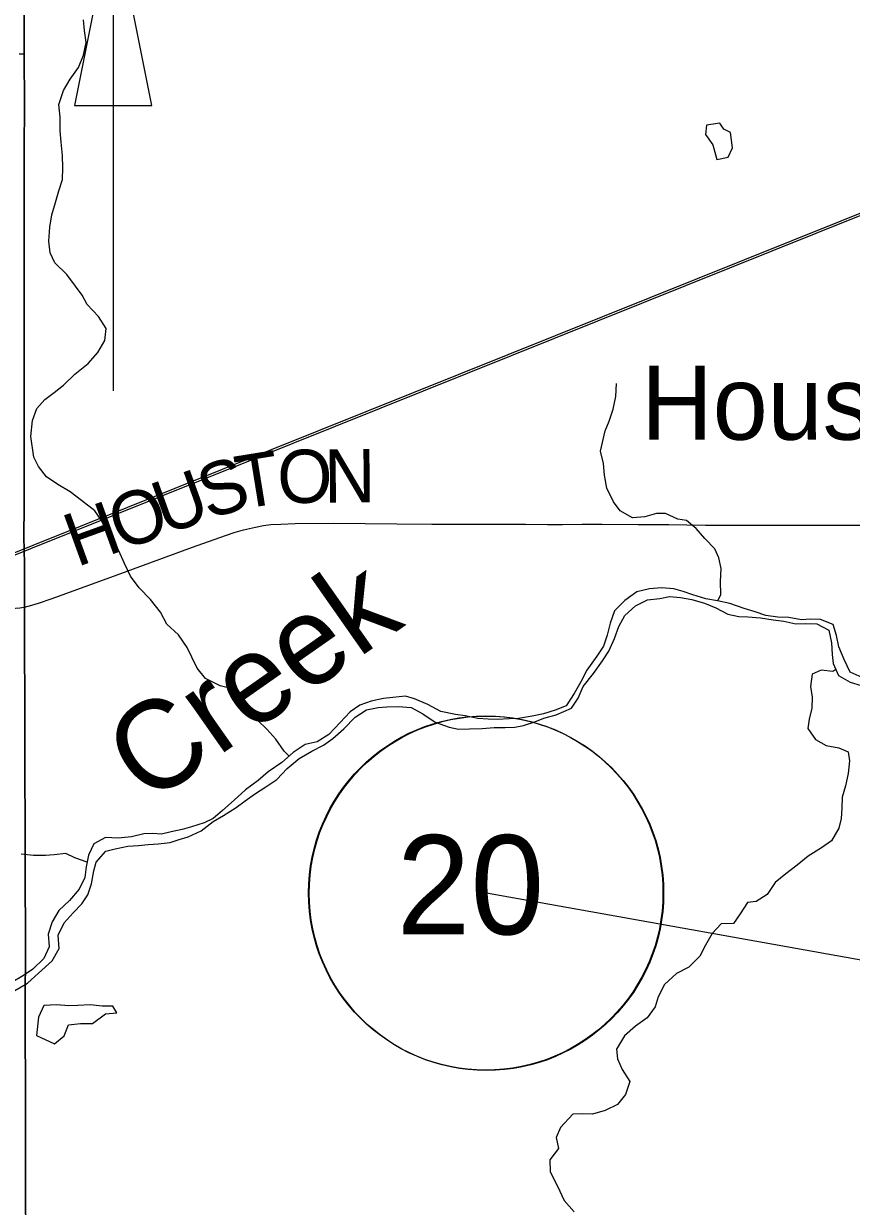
# Model space of a CAD drawing. Extents: x -87 to 2145, y -2128 to 440.
# Drawn here: x 81.45 to 104.8, y 285.55 to 318.92 of the extents above; entities that cross this region are included whole.
import ezdxf

# ---------------------------------------------------------------- set-up
doc = ezdxf.new("R2010")
doc.units = 0
for name, color, linetype in [('BR_P_Gen_Text', 7, 'Continuous'), ('Default', 7, 'Continuous'), ('GM_X_County_Road', 7, 'Continuous'), ('GM_X_County_Road_Text', 7, 'Continuous'), ('GM_X_Minor_Lake', 7, 'Continuous'), ('GM_X_Minor_River', 7, 'Continuous'), ('GM_X_Minor_River_Text', 7, 'Continuous'), ('GM_X_Rail_Line', 7, 'Continuous'), ('GM_X_State_Route', 7, 'Continuous'), ('GM_X_Township_Road', 7, 'Continuous'), ('GM_X_Unincorporated_Text', 7, 'Continuous'), ('SH_Masking', 7, 'Continuous'), ('SH_Text', 7, 'Continuous')]:
    doc.layers.add(name, color=color, linetype=linetype)

msp = doc.modelspace()

# ---------------------------------------------------------------- linework, layer by layer
at = {"layer": 'BR_P_Gen_Text'}
msp.add_lwpolyline([(82.88, 316.612), (85.062, 316.612), (83.971, 322.068)], close=True, dxfattribs=at)
at = {"layer": 'Default'}
msp.add_line((83.971, 322.068), (83.971, 308.561), dxfattribs=at)
for points in [[(81.467, 319.469), (81.46, 318.468), (81.462, 318.07), (81.468, 316.598), (81.464, 315.401), (81.464, 313.597), (81.465, 312.432), (81.463, 311.268), (81.467, 310.021), (81.463, 309.267), (81.465, 308.184), (81.467, 307.167), (81.46, 306.331), (81.465, 305.313), (81.457, 304.444), (81.468, 303.691), (81.474, 302.46), (81.476, 302.116), (81.474, 301.066), (81.478, 300.066), (81.481, 298.343), (81.483, 297.491), (81.489, 296.605), (81.491, 294.981), (81.499, 292.996), (81.499, 292.372), (81.493, 291.714)], [(81.493, 291.714), (81.492, 291.503), (81.496, 290.339), (81.501, 289.076), (81.502, 287.648), (81.497, 286.763), (81.501, 285.943), (81.509, 284.696), (81.516, 283.548), (81.516, 282.334), (81.518, 280.924), (81.526, 279.825), (81.522, 278.972), (81.521, 278.431), (81.529, 277.184), (81.528, 276.298), (81.527, 275.79), (81.535, 274.822), (81.533, 273.69), (81.535, 272.944)]]:
    msp.add_lwpolyline(points, dxfattribs=at)
at = {"layer": 'GM_X_County_Road'}
for points in [[(81.474, 302.46), (81.676, 302.511), (81.866, 302.568), (82.254, 302.701), (84.09, 303.365), (86.215, 304.145), (87.141, 304.477), (87.389, 304.56), (87.656, 304.638), (87.99, 304.717), (88.214, 304.757), (88.424, 304.785), (88.701, 304.803), (89.11, 304.816), (90.192, 304.822), (91.98, 304.81), (92.964, 304.802), (93.669, 304.798), (94.03, 304.797), (94.505, 304.796), (95.03, 304.796), (95.604, 304.795), (96.227, 304.792), (96.654, 304.792), (97.211, 304.794), (97.768, 304.794), (98.785, 304.793), (99.654, 304.789), (100.162, 304.779), (100.687, 304.772), (101.606, 304.769), (102.229, 304.769), (103.13, 304.768), (103.573, 304.769), (103.933, 304.772), (104.211, 304.771), (104.736, 304.769), (105.293, 304.771)], [(77.458, 302.074), (77.604, 302.126), (77.9, 302.219), (78.137, 302.282), (78.328, 302.323), (78.521, 302.356), (78.764, 302.386), (79.024, 302.406), (79.466, 302.42), (79.941, 302.427), (80.433, 302.423), (81.023, 302.42), (81.222, 302.424), (81.338, 302.434), (81.452, 302.455), (81.474, 302.46)]]:
    msp.add_lwpolyline(points, dxfattribs=at)
at = {"layer": 'GM_X_Minor_Lake'}
msp.add_line((84.075, 291.009), (83.966, 291.195), dxfattribs=at)
for points in [[(100.713, 316.053), (100.688, 315.793), (100.892, 315.498), (101.004, 315.085), (101.326, 315.149)], [(101.326, 315.149), (101.451, 315.417), (101.389, 315.85), (101.201, 315.943), (101.094, 316.116), (100.713, 316.053)], [(83.966, 291.195), (83.66, 291.201), (83.33, 291.239), (82.978, 291.216), (82.727, 291.211), (82.376, 291.238), (82.014, 291.216), (81.866, 290.886), (81.809, 290.372)], [(81.809, 290.372), (82.323, 290.131), (82.588, 290.357), (82.715, 290.667), (83.048, 290.711), (83.389, 290.713), (83.756, 290.978), (84.075, 291.009)]]:
    msp.add_lwpolyline(points, dxfattribs=at)
at = {"layer": 'GM_X_Minor_River'}
for points in [[(81.652, 307.268), (81.699, 307.72), (81.825, 308.059), (82.049, 308.315), (82.313, 308.512), (82.576, 308.718), (82.892, 309.033), (83.267, 309.328), (83.542, 309.644), (83.738, 309.981), (83.774, 310.321), (83.559, 310.656), (83.244, 311.001), (83.098, 311.264), (82.912, 311.518), (82.667, 311.843), (82.332, 312.169), (82.197, 312.452), (82.162, 312.783), (82.188, 313.183), (82.244, 313.523), (82.35, 313.872), (82.445, 314.201), (82.541, 314.521), (82.556, 314.851), (82.542, 315.202), (82.508, 315.573), (82.483, 315.894), (82.479, 316.285), (82.445, 316.637), (82.571, 317.035), (82.757, 317.353), (82.992, 317.68), (83.138, 318.028), (83.214, 318.388), (83.17, 318.729), (83.135, 319.03)], [(97.721, 306.862), (97.852, 307.434), (97.967, 307.703), (98.083, 308.042), (98.158, 308.401), (98.175, 308.772)], [(88.941, 298.256), (88.802, 298.398), (88.568, 298.735), (88.313, 299.012), (88.057, 299.259), (87.852, 299.556), (87.597, 299.863), (87.292, 300.162), (86.993, 300.239), (86.575, 300.439), (86.34, 300.736), (86.196, 301.041), (86.061, 301.316), (85.818, 301.674), (85.492, 301.973), (85.309, 302.319), (85.025, 302.677), (84.711, 303.006), (84.466, 303.334), (84.293, 303.69), (84.13, 304.046), (83.994, 304.301), (83.81, 304.627), (83.645, 304.902), (83.46, 305.178), (83.085, 305.468), (82.758, 305.707), (82.411, 305.915), (82.094, 306.134), (81.87, 306.43), (81.734, 306.685), (81.652, 307.272)], [(101.034, 302.633), (101.116, 302.815), (101.114, 303.178), (101.132, 303.55), (101.067, 303.844), (100.952, 304.098), (100.667, 304.396), (100.422, 304.673), (100.155, 304.901), (99.905, 304.936), (99.557, 305.104), (99.306, 305.1), (98.973, 305.006), (98.631, 304.973), (98.283, 305.171), (98.088, 305.427), (97.905, 305.814), (97.842, 306.178), (97.809, 306.511), (97.721, 306.862)], [(90.8, 299.353), (91.126, 299.558), (91.449, 299.622), (91.7, 299.647), (92.022, 299.65), (92.383, 299.623), (92.71, 299.444), (93.057, 299.216), (93.456, 299.066), (93.716, 299.01), (94.027, 299.024), (94.389, 299.037), (94.721, 299.06), (95.032, 299.064), (95.304, 299.068), (95.556, 299.113), (95.869, 299.217), (96.122, 299.323), (96.476, 299.416), (96.902, 299.609), (97.098, 299.887), (97.236, 300.216), (97.525, 300.583), (97.783, 300.94), (97.96, 301.219), (98.118, 301.568), (98.245, 301.908), (98.412, 302.217), (98.709, 302.493), (99.054, 302.667), (99.396, 302.7), (99.669, 302.755), (99.98, 302.728), (100.3, 302.671), (100.659, 302.573), (100.978, 302.435), (101.315, 302.257), (101.625, 302.19), (101.886, 302.185), (102.237, 302.157), (102.598, 302.1), (102.898, 302.063), (103.238, 301.985), (103.499, 302), (103.83, 301.983), (104.168, 301.805), (104.241, 301.451), (104.264, 301.118), (104.289, 300.866), (104.443, 300.53), (104.77, 300.342), (105.08, 300.245)], [(105.104, 300.476), (104.766, 300.624), (104.603, 300.98), (104.45, 301.336), (104.386, 301.659), (104.292, 301.964), (103.933, 302.112), (103.652, 302.118), (103.391, 302.103), (103.041, 302.161), (102.73, 302.177), (102.389, 302.225), (102.09, 302.322), (101.781, 302.419), (101.372, 302.558), (101.022, 302.636), (100.692, 302.693), (100.333, 302.801), (100.053, 302.898), (99.794, 302.974), (99.443, 303.001), (99.111, 302.978), (98.748, 302.885), (98.411, 302.64), (98.124, 302.354), (97.996, 302.004), (97.909, 301.663), (97.812, 301.353), (97.625, 301.075), (97.336, 300.678), (97.168, 300.349), (96.981, 300.02), (96.752, 299.672), (96.448, 299.548), (96.115, 299.444), (95.792, 299.38), (95.409, 299.318), (95.148, 299.303), (94.816, 299.29)], [(104.365, 300.701), (104.284, 300.644), (103.954, 300.681), (103.7, 300.566), (103.653, 300.214), (103.697, 299.921), (103.69, 299.609), (103.614, 299.298), (103.578, 299.037), (103.792, 298.72), (104.09, 298.553), (104.45, 298.485), (104.709, 298.379), (104.754, 298.116), (104.716, 297.764), (104.639, 297.413), (104.542, 297.093), (104.535, 296.781), (104.519, 296.489), (104.453, 296.218), (104.245, 295.86), (103.96, 295.664), (103.583, 295.43), (103.276, 295.175), (102.95, 294.93), (102.654, 294.684), (102.426, 294.346), (102.12, 294.151), (101.869, 294.126), (101.661, 293.808), (101.475, 293.53), (101.133, 293.517), (100.876, 293.25), (100.689, 292.922), (100.531, 292.613), (100.214, 292.297), (99.868, 292.123), (99.53, 291.807), (99.352, 291.458), (99.266, 291.178), (99.039, 290.871), (98.713, 290.636), (98.406, 290.36), (98.177, 289.982), (98.201, 289.709), (98.336, 289.415), (98.549, 289.068), (98.431, 288.707), (98.204, 288.42), (97.859, 288.256), (97.496, 288.153), (97.205, 288.159), (96.943, 288.154), (96.594, 287.779), (96.478, 287.489), (96.542, 287.185), (96.294, 286.858), (96.307, 286.525), (96.509, 286.118), (96.702, 285.711), (96.986, 285.393)], [(94.816, 299.29), (94.555, 299.295), (94.264, 299.311), (93.904, 299.389), (93.634, 299.425), (93.224, 299.514), (92.857, 299.713), (92.478, 299.872), (92.219, 299.948), (91.866, 299.905), (91.605, 299.881), (91.252, 299.807), (90.938, 299.693), (90.663, 299.507), (90.375, 299.201), (90.057, 298.865), (89.731, 298.66), (89.388, 298.577), (89.052, 298.352), (88.735, 298.077), (88.348, 297.813), (88.062, 297.567), (87.705, 297.302), (87.387, 297.007), (87.06, 296.721), (86.794, 296.495), (86.54, 296.37), (86.186, 296.256), (85.924, 296.181), (85.611, 296.117), (85.339, 296.052), (85.088, 296.068), (84.837, 296.063), (84.493, 295.979), (84.111, 295.937), (83.76, 295.954), (83.425, 295.78), (83.277, 295.461), (83.21, 295.13), (83.174, 294.828), (83.016, 294.499), (82.739, 294.182), (82.441, 293.896), (82.254, 293.578), (82.136, 293.228), (82.169, 292.875), (82.022, 292.545), (81.704, 292.24), (81.449, 292.064), (81.093, 291.859)], [(81.199, 291.636), (81.555, 291.85), (81.872, 292.125), (82.251, 292.48), (82.449, 292.828), (82.427, 293.202), (82.595, 293.551), (82.842, 293.828), (83.088, 294.084), (83.264, 294.343), (83.361, 294.653), (83.429, 295.014), (83.494, 295.265), (83.772, 295.571), (84.034, 295.636), (84.387, 295.709), (84.689, 295.733), (84.961, 295.758), (85.243, 295.782), (85.585, 295.815), (85.838, 295.901), (86.09, 295.976), (86.455, 296.15), (86.792, 296.405), (87.087, 296.58), (87.443, 296.804), (87.698, 296.99), (87.963, 297.176), (88.279, 297.391), (88.594, 297.596), (88.882, 297.902), (89.219, 298.188), (89.575, 298.392), (89.91, 298.566), (90.175, 298.752), (90.482, 299.028), (90.8, 299.353)], [(83.238, 295.265), (82.894, 295.388), (82.636, 295.504), (82.314, 295.471), (82.062, 295.446), (81.731, 295.453), (81.38, 295.49)]]:
    msp.add_lwpolyline(points, dxfattribs=at)
at = {"layer": 'GM_X_Rail_Line'}
for points in [[(30, 287.522), (45.071, 290.572), (48.056, 291.256), (50.052, 291.746), (51.735, 292.258), (53.316, 292.788), (55.455, 293.588), (80.376, 303.673), (111.189, 316.036), (127.457, 322.637), (139.82, 328.319), (148.542, 332.369), (157.168, 336.397), (162.099, 338.704), (163.793, 339.451), (165.536, 340.154), (166.714, 340.588), (168.403, 341.164), (169.558, 341.524), (170.808, 341.89), (172.03, 342.209), (173.276, 342.51)], [(30, 287.459), (45.084, 290.511), (48.071, 291.195), (50.068, 291.686), (51.755, 292.198), (53.337, 292.729), (55.478, 293.529), (80.399, 303.615), (111.212, 315.978), (127.482, 322.579), (139.846, 328.262), (148.568, 332.313), (157.194, 336.341), (162.125, 338.648), (163.817, 339.394), (165.559, 340.096), (166.735, 340.529), (168.422, 341.104), (169.576, 341.465), (170.825, 341.83), (172.046, 342.149), (173.29, 342.45)]]:
    msp.add_lwpolyline(points, dxfattribs=at)
at = {"layer": 'GM_X_State_Route'}
for points in [[(81.493, 291.714), (81.499, 292.372), (81.499, 292.996), (81.491, 294.981), (81.489, 296.605), (81.483, 297.491), (81.481, 298.343), (81.478, 300.066), (81.474, 301.066), (81.476, 302.116), (81.474, 302.46), (81.468, 303.691), (81.457, 304.444), (81.465, 305.313), (81.46, 306.331), (81.467, 307.167), (81.465, 308.184), (81.463, 309.267), (81.467, 310.021), (81.463, 311.268), (81.465, 312.432), (81.464, 313.597), (81.464, 315.401), (81.468, 316.598), (81.462, 318.07), (81.46, 318.468), (81.467, 319.469)], [(81.535, 272.944), (81.533, 273.69), (81.535, 274.822), (81.527, 275.79), (81.528, 276.298), (81.529, 277.184), (81.521, 278.431), (81.522, 278.972), (81.526, 279.825), (81.518, 280.924), (81.516, 282.334), (81.516, 283.548), (81.509, 284.696), (81.501, 285.943), (81.497, 286.763), (81.502, 287.648), (81.501, 289.076), (81.496, 290.339), (81.492, 291.503), (81.493, 291.714)]]:
    msp.add_lwpolyline(points, dxfattribs=at)
at = {"layer": 'GM_X_Township_Road'}
msp.add_lwpolyline([(81.32, 318.071), (81.462, 318.07)], dxfattribs=at)
at = {"layer": 'SH_Masking'}
msp.add_circle((94.506, 294.384), 5, dxfattribs=at)
at = {"layer": 'SH_Text'}
msp.add_line((111.526, 291.344), (94.506, 294.384), dxfattribs=at)
msp.add_circle((94.487, 294.392), 5, dxfattribs=at)

# ---------------------------------------------------------------- texts
at = {"layer": 'GM_X_County_Road_Text'}
for s, rotation, p in [('T', 9.1978, (87.563, 305.214)), ('O', 0.8288, (88.613, 305.388)), ('N', 0.428, (89.93, 305.407)), ('S', 17.5845, (86.655, 304.922)), ('U', 19.7425, (85.427, 304.48)), ('O', 19.9321, (84.187, 304.031)), ('H', 19.9338, (82.946, 303.581))]:
    msp.add_text(s, height=1.5, rotation=rotation, dxfattribs=at).set_placement(p)
at = {"layer": 'GM_X_Minor_River_Text'}
msp.add_text('Creek', height=2.4997, rotation=35.0106, dxfattribs=at).set_placement((84.946, 296.844))
at = {"layer": 'GM_X_Unincorporated_Text'}
msp.add_text('Houston', height=2.085, rotation=0, dxfattribs=at).set_placement((98.878, 307.182))
at = {"layer": 'SH_Text'}
msp.add_text('20', height=2.8, rotation=360, dxfattribs=at).set_placement((91.973, 293.224))

doc.saveas('drawing.dxf')
